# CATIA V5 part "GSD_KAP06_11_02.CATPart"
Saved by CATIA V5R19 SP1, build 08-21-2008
Part number: GSD_BLEND_02
Definition: Beispielmodell für Funktion Übergang / Blend - Schließpunkte.
Description: CATIA V5 Flächenmodellierung  Copyright (c) 2009 Maik Hertha IT Consultants
Bounding box of the stored display mesh (mm): x -83.184 to 84.357, y -79.412 to 63.099, z 10.158 to 100.578
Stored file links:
  \GSD_BUCH_UEBUNG\GSD_KAP06_11_02.CATPart
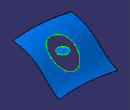
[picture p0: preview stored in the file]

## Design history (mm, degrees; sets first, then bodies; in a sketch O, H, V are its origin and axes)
AxisSystem1 "Absolute Axis System": origin (0, 0, 0), X (1, 0, 0), Y (0, 1, 0), Z (0, 0, 1)
Set1 "Blend Closing Points"
  Plane1: type Equation, A 1, B 0, C 0, Length 10
  Plane2: type Equation, A 0, B 1, C 0, Length 10
  Sketch1 on Plane1, origin (10, 0, 0), H (0, 1, 0), V (0, 0, 1)
    spline S1 through (-65.2612, 78.1032) (-9.8286, 51.5504) (16.7565, 27.5399) (69.3609, -3.2501)
  Sketch2 on Plane2, origin (0, 10, 0), H (-1, 0, 0), V (0, 0, 1)
    spline S1 through (-84.3573, 57.652) (-27.1326, 60.1922) (83.1839, 48.4436)
  Sweep1: type Unspec, Guide Sketch1, Profile Sketch2
  Plane3: type Equation, A 0, B 0, C 1, Length 10
  Point1: type OnPlane, Support Plane3, Direction (1, 0, 0), H 10, V -5
  Project1: Support Sweep1, Direction (0, 0, 1), ToProject Point1
  Plane4: type OffsetPt, RefPlane Plane3, RefPoint Project1
  Sketch3 on Plane4, origin (10, -5, 73.0975), H (-1, 0, 0), V (0, -1, 0)
    circle A1 centre (0, 0) radius 15
    point P1 (0, 0)
    construction line L1 (0, 50.1877) -> (0, -40.9217)
    construction line L2 (-38.9266, 0) -> (47.295, 0)
    reference projected point E1 (0, 0) from Point1
    radius A1 = 15
    vertical: L1 V
    horizontal: L2 H
    coincidence: P1 L1, P1 L2, E1 P1
  Split1: ToCut Plane4, Intersections {intersect ToIntersect1 Plane4, ToIntersect2 Sketch3}, Cutting Sketch3
  Extrude1: Lim1 40, Lim2 50, Element1 {intersect ToIntersect1 Plane4, ToIntersect2 Sketch3}, Direction Plane4
  Offset1: Length 20, Offset Extrude1
  Split2: ToCut Sweep1, Intersections {intersect ToIntersect1 Sweep1, ToIntersect2 Offset1}, Cutting Offset1
Body1 (main body)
